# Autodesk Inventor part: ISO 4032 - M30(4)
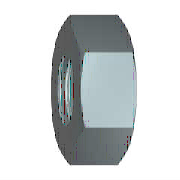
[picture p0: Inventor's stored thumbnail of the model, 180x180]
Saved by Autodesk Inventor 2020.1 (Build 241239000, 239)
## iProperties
Created: 2019-01
Part Number: ISO 4032 - M30(4)
Material: Edelstahl, 440C
Description: Sechskantmuttern, Typ 1 - Produktklasse A und B
Document SubType Name: Modeling
Standard: ISO 4032
Designer: lutzd
Standard Revision: Fourth edition 2012-12-15
Standards Organization: ISO
Language: de-DE
Size Designation: M30
Categories: <MemberInstance><Categories><Category DisplayName="Verbindungselemente" InternalName="e4da775c-781d-43d5-af7c-5136215cf5a6" Mnemonic="FSTN"><Category DisplayNam
Mass: 249.433 g
Surface Area: 82.477 cm^2
Volume: 32.185 cm^3
Density: 7.75 g/cm^3
Appearance: Halbpoliert
IsCustomPart: 0
Author: lutzd
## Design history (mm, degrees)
body "Solid1"
sketch "Skizze1"
  geometry: L1 (-26.558, 0)-(-13.279, 23); L2 (-13.279, 23)-(13.279, 23); L3 (13.279, 23)-(26.558, 0); L4 (26.558, 0)-(13.279, -23); L5 (13.279, -23)-(-13.279, -23); L6 (-13.279, -23)-(-26.558, 0); 2 further points
  constraints: 12 end point, 1 coincident, 1 horizontal, 11 other
  dimensions: "d0" = 53.11622 distance of L3.end L1.start (= 1.1547 x SW)
workaxis "Work Axis1"
workplane "Work Plane1"
extrude "Körper" new body sketch "Skizze1" distance "d1" = 25.6 (= KOH); taper "d2" = 0 deg
sketch "Skizze2"
  geometry: L1 (0, 13.279)-(0, 26.558) reference; L2 (0, 26.558)-(25.6, 26.558) reference; L3 (25.6, 13.279)-(25.6, 26.558) reference; L4 (-5.12, 0)-(30.72, 0) reference; L5 (2.978, 26.558)-(0, 21.4); L6 (22.622, 26.558)-(25.6, 21.4)
  constraints: 4 end point, 4 point on line
  dimensions: "d3" = 30 deg angle of L1 L5 (= ANG1); "d4" = 30 deg angle of L3 L6 (= ANG2); "d5" = 42.8 diameter of L5.end L4 (= SW0); "d6" = 42.8 diameter of L6.end L4 (= SW01)
revolve "Fase1" stored, may be unused: angle "d7" = 90 deg
sketch "Skizze3"
  geometry: 4 further points
  constraints: 1 coincident, 1 other
hole "Gewinde" sketch "Skizze3" diameter "d25" = 26.211; stored, may be unused: countersink angle "d29" = 82 deg, drill point angle "d31" = 118 deg; dims "d26" = 6, "d27" = 4, "d28" = 2, "d30" = 8
chamfer "Fase2" distance "d8" = 1.89443 (= -0.5 x GD1 + 0.5 x NND); stored, may be unused: angle "d9" = 30 deg, second distance "d40" = 1.89443 (= -0.5 x GD1 + 0.5 x NND)
chamfer "Fase3" distance "d10" = 1.89443 (= -0.5 x GD1 + 0.5 x NND); stored, may be unused: angle "d11" = 30 deg, second distance "d41" = 1.89443 (= -0.5 x GD1 + 0.5 x NND)
other parameters: "ANG1" = 30 deg [user parameter; used in 1 equation term], "ANG2" = 30 deg [user parameter; used in 1 equation term], "KOH" = 25.6 [user parameter; used in 1 equation term], "SW" = 46 [user parameter; used in 2 equation terms], "SW0" = 42.8 [user parameter; used in 2 equation terms], "SW01" = 42.8 (= SW0) [user parameter; used in 1 equation term], "GD1" = 26.21114 (computed from THREADDIA, PTC, TOA) [user parameter; used in 4 equation terms], "d13" = 0, "d14" = 0, "d39" = 0, "d42" = 0, "GUL" = 1.89443 (= 0.541266 x PTC) [user parameter], "TPU" = 2.85714 (computed from PTC) [user parameter], "TOA" = 30 deg [user parameter; used in 1 equation term], "PTC" = 3.5 [user parameter; used in 4 equation terms], "E0" = 53.13 (= 1.155 x SW) [user parameter], "GAL" = 1.89443 (= 0.541266 x PTC) [user parameter]
